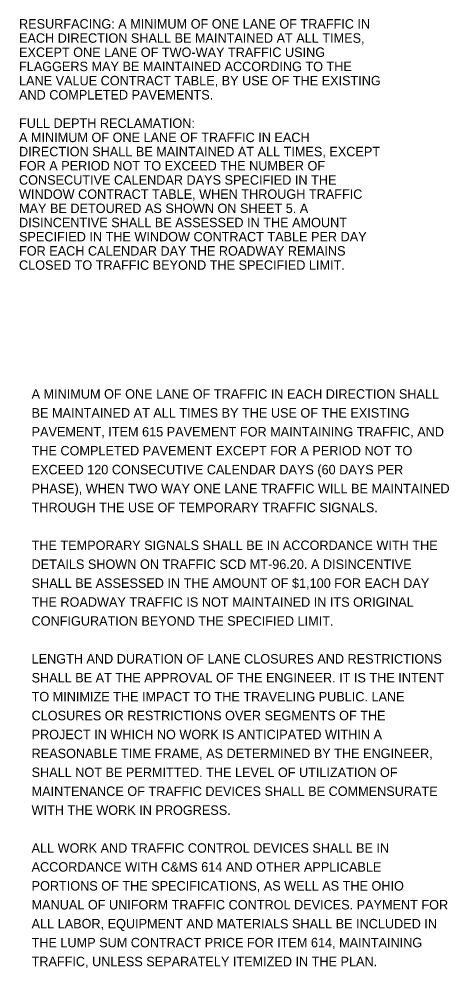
# Model space of a CAD drawing. Extents: x -21.1 to 72.2, y 0 to 46.6.
# Drawn here: x -21.06 to -14.71, y 15.49 to 29.53 of the extents above; entities that cross this region are included whole.
import ezdxf

# ---------------------------------------------------------------- set-up
doc = ezdxf.new("R2010")
doc.units = 0
doc.layers.add('SH_Text', color=7, linetype='Continuous')

msp = doc.modelspace()

# ---------------------------------------------------------------- texts
at = {"layer": 'SH_Text'}
for s, p in [('RESURFACING: A MINIMUM OF ONE LANE OF TRAFFIC IN ', (-21.064, 29.389)), ('EACH DIRECTION SHALL BE MAINTAINED AT ALL TIMES, ', (-21.064, 29.179)), ('EXCEPT ONE LANE OF TWO-WAY TRAFFIC USING ', (-21.064, 28.969)), ('FLAGGERS MAY BE MAINTAINED ACCORDING TO THE ', (-21.064, 28.759)), ('LANE VALUE CONTRACT TABLE, BY USE OF THE EXISTING ', (-21.064, 28.549)), ('AND COMPLETED PAVEMENTS.', (-21.064, 28.339)), ('FULL DEPTH RECLAMATION:', (-21.064, 27.919)), ('A MINIMUM OF ONE LANE OF TRAFFIC IN EACH ', (-21.064, 27.709)), ('DIRECTION SHALL BE MAINTAINED AT ALL TIMES, EXCEPT ', (-21.064, 27.499)), ('FOR A PERIOD NOT TO EXCEED THE NUMBER OF ', (-21.064, 27.289)), ('CONSECUTIVE CALENDAR DAYS SPECIFIED IN THE ', (-21.064, 27.079)), ('WINDOW CONTRACT TABLE, WHEN THROUGH TRAFFIC ', (-21.064, 26.869)), ('MAY BE DETOURED AS SHOWN ON SHEET 5. A ', (-21.064, 26.659)), ('DISINCENTIVE SHALL BE ASSESSED IN THE AMOUNT ', (-21.064, 26.449)), ('SPECIFIED IN THE WINDOW CONTRACT TABLE PER DAY ', (-21.064, 26.239)), ('FOR EACH CALENDAR DAY THE ROADWAY REMAINS ', (-21.064, 26.029)), ('CLOSED TO TRAFFIC BEYOND THE SPECIFIED LIMIT.', (-21.064, 25.819)), ('A MINIMUM OF ONE LANE OF TRAFFIC IN EACH DIRECTION SHALL ', (-20.878, 23.912)), ('BE MAINTAINED AT ALL TIMES BY THE USE OF THE EXISTING ', (-20.878, 23.632)), ('PAVEMENT, ITEM 615 PAVEMENT FOR MAINTAINING TRAFFIC, AND ', (-20.878, 23.352)), ('THE COMPLETED PAVEMENT EXCEPT FOR A PERIOD NOT TO ', (-20.878, 23.072)), ('EXCEED 120 CONSECUTIVE CALENDAR DAYS (60 DAYS PER ', (-20.878, 22.792)), ('PHASE), WHEN TWO WAY ONE LANE TRAFFIC WILL BE MAINTAINED ', (-20.878, 22.512)), ('THROUGH THE USE OF TEMPORARY TRAFFIC SIGNALS. ', (-20.878, 22.232)), ('THE TEMPORARY SIGNALS SHALL BE IN ACCORDANCE WITH THE ', (-20.878, 21.672)), ('DETAILS SHOWN ON TRAFFIC SCD MT-96.20. A DISINCENTIVE ', (-20.878, 21.392)), ('SHALL BE ASSESSED IN THE AMOUNT OF $1,100 FOR EACH DAY ', (-20.878, 21.112)), ('THE ROADWAY TRAFFIC IS NOT MAINTAINED IN ITS ORIGINAL ', (-20.878, 20.832)), ('CONFIGURATION BEYOND THE SPECIFIED LIMIT.', (-20.878, 20.552)), ('LENGTH AND DURATION OF LANE CLOSURES AND RESTRICTIONS ', (-20.878, 19.992)), ('SHALL BE AT THE APPROVAL OF THE ENGINEER. IT IS THE INTENT ', (-20.878, 19.712)), ('TO MINIMIZE THE IMPACT TO THE TRAVELING PUBLIC. LANE ', (-20.878, 19.432)), ('CLOSURES OR RESTRICTIONS OVER SEGMENTS OF THE ', (-20.878, 19.152)), ('PROJECT IN WHICH NO WORK IS ANTICIPATED WITHIN A ', (-20.878, 18.872)), ('REASONABLE TIME FRAME, AS DETERMINED BY THE ENGINEER, ', (-20.878, 18.592)), ('SHALL NOT BE PERMITTED. THE LEVEL OF UTILIZATION OF ', (-20.878, 18.312)), ('MAINTENANCE OF TRAFFIC DEVICES SHALL BE COMMENSURATE ', (-20.878, 18.032)), ('WITH THE WORK IN PROGRESS.', (-20.878, 17.752)), ('ALL WORK AND TRAFFIC CONTROL DEVICES SHALL BE IN ', (-20.878, 17.192)), ('ACCORDANCE WITH C&MS 614 AND OTHER APPLICABLE ', (-20.878, 16.912)), ('PORTIONS OF THE SPECIFICATIONS, AS WELL AS THE OHIO ', (-20.878, 16.632)), ('MANUAL OF UNIFORM TRAFFIC CONTROL DEVICES. PAYMENT FOR ', (-20.878, 16.352)), ('ALL LABOR, EQUIPMENT AND MATERIALS SHALL BE INCLUDED IN ', (-20.878, 16.072)), ('THE LUMP SUM CONTRACT PRICE FOR ITEM 614, MAINTAINING ', (-20.878, 15.792)), ('TRAFFIC, UNLESS SEPARATELY ITEMIZED IN THE PLAN.', (-20.878, 15.512))]:
    msp.add_text(s, height=0.14, dxfattribs=at).set_placement(p)

doc.saveas('drawing.dxf')
